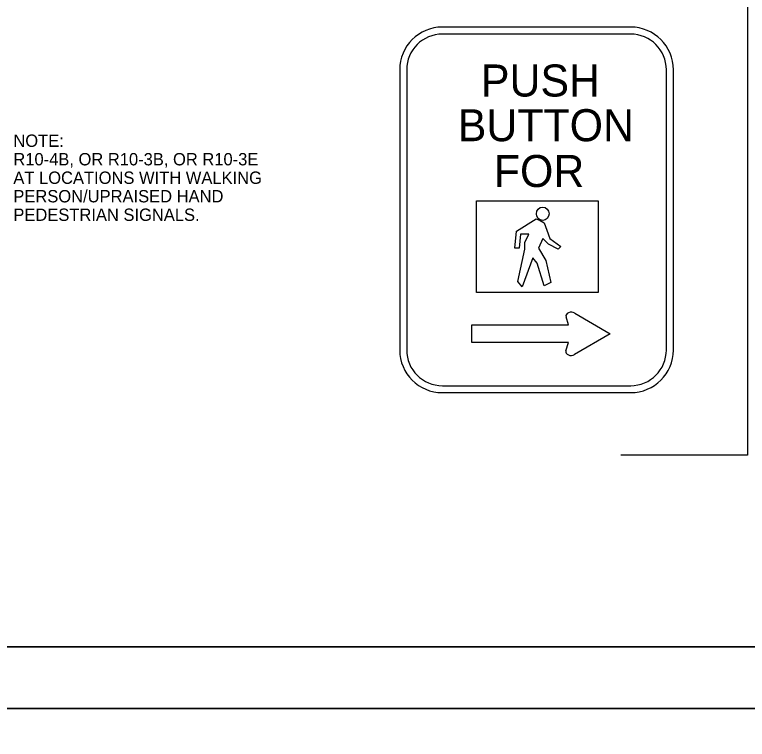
# Model space of a CAD drawing. Extents: x -344 to 940, y 22 to 1233.
# Drawn here: x 84.3 to 262.3, y 608.7 to 784.9 of the extents above; entities that cross this region are included whole.
import ezdxf

# ---------------------------------------------------------------- set-up
doc = ezdxf.new("R2010")
doc.units = 0
for name, color, linetype in [('1', 7, 'Continuous'), ('2', 7, 'Continuous'), ('PLT-BNDY', 7, 'Continuous')]:
    doc.layers.add(name, color=color, linetype=linetype)

msp = doc.modelspace()

# ---------------------------------------------------------------- linework, layer by layer
at = {"layer": '1'}
for p, q in [((861.86, 631.17), (75.86, 631.17)), ((75.86, 631.17), (661.86, 631.17))]:
    msp.add_line(p, q, dxfattribs=at)
at = {"layer": '2'}
for p, q in [((262.33, 910.3), (262.33, 677.76)), ((233.98, 781.84), (188.22, 781.84)), ((233.98, 780.14), (188.22, 780.14)), ((177.85, 771.47), (177.85, 703.33)), ((179.55, 771.47), (179.55, 703.33)), ((242.65, 703.33), (242.65, 771.47)), ((244.35, 703.33), (244.35, 771.47)), ((196.48, 717.34), (196.48, 739.59)), ((196.48, 739.59), (226.1, 739.59)), ((226.1, 739.59), (226.1, 717.34)), ((226.1, 717.34), (196.48, 717.34)), ((220.39, 712.31), (229.03, 707.28)), ((218.91, 709.41), (218.27, 711.41)), ((195.38, 705.15), (195.38, 709.42)), ((195.38, 709.42), (205.28, 709.41)), ((205.28, 709.41), (218.91, 709.41)), ((229.03, 707.28), (220.36, 702.24)), ((205.28, 705.16), (195.38, 705.15)), ((218.91, 705.16), (205.28, 705.16)), ((218.21, 703.14), (218.91, 705.16)), ((188.22, 694.66), (233.98, 694.66)), ((188.22, 692.96), (233.98, 692.96)), ((262.33, 677.76), (231.55, 677.76))]:
    msp.add_line(p, q, dxfattribs=at)
msp.add_lwpolyline([(216.98, 728.46), (216.35, 727.84), (213.98, 729.09), (212.6, 730.46), (211.6, 728.09), (213.35, 725.09), (214.6, 719.71), (212.98, 718.96), (211.23, 724.46), (210.23, 725.71), (207.6, 718.71), (206.6, 719.96), (208.23, 727.84), (208.23, 728.09), (208.23, 728.46), (208.23, 728.84), (208.23, 729.09), (208.23, 729.46), (209.23, 731.46), (207.23, 731.46), (206.85, 728.09), (205.85, 728.09), (206.23, 732.21), (210.98, 735.21), (211.98, 734.84), (212.98, 734.21), (213.6, 732.46), (214.35, 730.46)], close=True, dxfattribs=at)
for centre, radius, start, end in [((188.22, 771.47), 10.37, 90, 180), ((233.98, 771.47), 10.37, 0, 90), ((188.22, 771.47), 8.67, 90, 180), ((233.98, 771.47), 8.67, 0, 90), ((188.22, 703.33), 10.37, 180, 270), ((188.22, 703.33), 8.67, 180, 270), ((233.98, 703.33), 10.37, 270, 0), ((233.98, 703.33), 8.67, 270, 0)]:
    msp.add_arc(centre, radius, start, end, dxfattribs=at)
msp.add_ellipse((212.62, 736.46), major_axis=(0, -1.62), ratio=0.957031, dxfattribs=at)
for centre, start_param, end_param in [((219.55, 711.58), 4.011799, 6.466875), ((219.48, 702.95), 6.078068, 8.589712)]:
    msp.add_ellipse(centre, major_axis=(-1.3, 0), ratio=0.7337, start_param=start_param, end_param=end_param, dxfattribs=at)
at = {"layer": 'PLT-BNDY'}
for points in [[(35.86, 1210.17), (876.86, 1210.17), (876.86, 616.17), (35.86, 616.17)], [(35.86, 616.17), (876.86, 616.17), (876.86, 22.17), (35.86, 22.17)]]:
    msp.add_lwpolyline(points, close=True, dxfattribs=at)

# ---------------------------------------------------------------- texts
at = {"layer": '2'}
for s, height, p in [('PUSH', 7.784, (197.6, 764.96)), ('BUTTON', 7.784, (191.98, 754.09)), ('NOTE:', 3, (83.98, 752.72)), ('R10-4B, OR R10-3B, OR R10-3E', 3, (83.98, 748.22)), ('FOR', 7.784, (200.73, 742.96)), ('AT LOCATIONS WITH WALKING', 3, (83.98, 743.72)), ('PERSON/UPRAISED HAND', 3, (83.98, 739.22)), ('PEDESTRIAN SIGNALS.', 3, (83.98, 734.72))]:
    msp.add_text(s, height=height, dxfattribs=at).set_placement(p)

doc.saveas('drawing.dxf')
